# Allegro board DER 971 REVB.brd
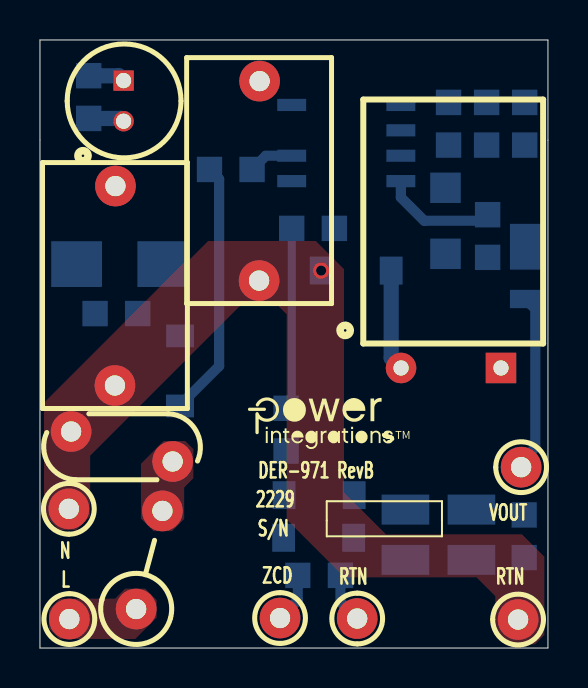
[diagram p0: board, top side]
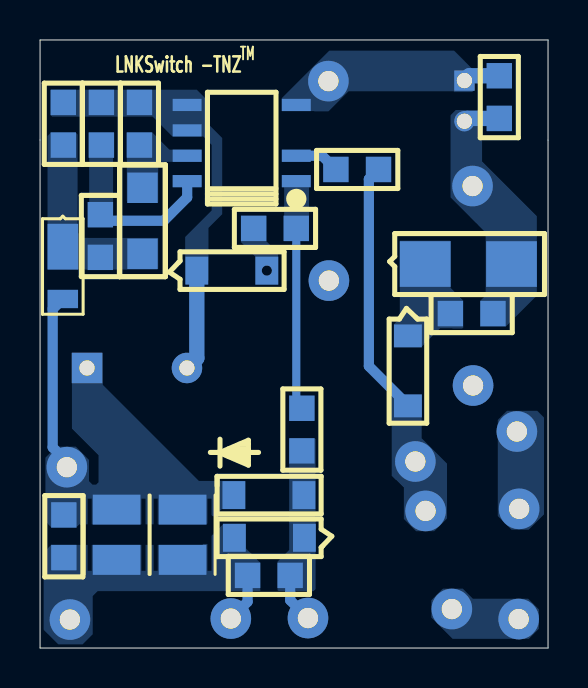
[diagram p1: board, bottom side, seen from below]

Outline 25.42 x 30.4 mm; copper layers: TOP, BOTTOM. Coordinates in mm from the lower left corner of the outline.
Outline path: 0,30.4 0,0 25.42,0 25.42,30.4 0,30.4

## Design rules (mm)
constraint set DEFAULT: min track width 0.508

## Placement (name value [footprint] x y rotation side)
C1  680 nF  [PINPCAPRAD12P3X7P3MM040]  10.97 28.37 270 top
C2  100 nF  [PISMC0805]  20.45 25.15 90 bottom
C3  10 uF  [PISMC0805]  24.26 25.15 90 bottom
C4  47 uF  [PISMC1411]  18.29 5.66 270 bottom
C5  100 pF  [PISMC0805]  12.6 20.98 0 bottom
C6  680 nF  [PINPCAPRAD12P3X7P3MM040]  3.75 23.13 270 top
C7  100 pF  [PISMC0805]  12.9 3.63 0 bottom
C10  47 uF  [PISMC1411]  21.59 5.66 270 bottom
D1  SM4007PL-TP  [PI_SM_SOD-123_12]  7.01 15.61 270 bottom
D2  ES1004FL_R1_00001  [PI_SM_SOD-123_12]  17.58 18.87 180 bottom
D3  DFLR1400-7  [PISMDDFLR120012]  24.28 20.09 90 bottom
D4  SM4001PL-TP  [PI_SM_SOD-123_12]  15.72 7.65 180 bottom
D5  SM4001PL-TP  [PI_SM_SOD-123_12]  12.19 5.51 0 bottom
L1  1000 uH  [PI_CHOKE_RLB9012_D2]  23.07 14 180 top
L2  2.2 mH  [PI_CHOKE_RL5480-1_D2]  4.18 28.37 270 top
NOREF  -  []  0 0 90 top
NOREF#2  -  []  0 0 0 top
NOREF#3  -  []  9.86 12.42 0 top
NOREF#4  -  []  -155.86 54.23 0 top
NOREF#5  -  []  -233.68 -144.78 0 top
R1  4.99 k  [PISMR0805]  2.76 16.72 0 bottom
R2  1 M  [PISMR0805]  10.62 23.93 180 bottom
R3  2 k  [PISMR1206]  20.29 23.02 270 bottom
R4  39.2 k  [PISMR0805]  22.35 25.15 90 bottom
R5  33.2 k  [PISMR0805]  22.4 19.54 90 bottom
R6  100 k  [PISMR0805]  12.32 11.99 270 bottom
R7  20 k  [PISMR0805]  24.23 6.65 270 bottom
R8  4.7 k  [PISMR0805]  2.44 26.48 90 bottom
RF1  8.2  [PI12WRESD180LS575040]  4.81 1.95 75 top
RV1  140 Vac  [PI_NP_CAP_RAD_320X120LS200D040]  6.64 9.3 180 top
TP1  BLK  [PITPKEYSTONE100X100]  1.47 1.45 0 top
TP2  WHT  [PITPKEYSTONE100X100]  1.45 6.96 0 top
TP3  RED  [PITPKEYSTONE100X100]  24.08 9.04 90 top
TP4  BLUE  [PITPKEYSTONE100X100]  12.01 1.5 0 top
TP5  BLK  [PITPKEYSTONE100X100]  23.93 1.42 90 top
TP6  BLK  [PITPKEYSTONE100X100]  15.87 1.47 0 top
U1  LNK3302  [PISMSO8_NOP3]  12.6 23.35 90 bottom
VR1  SMAZ10-13-F  [PISMDO214AC12]  6.15 19.2 180 bottom

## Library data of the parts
C1-C3 C5-C7 = CAP NP
C4 C10 = CAP POL: User Part Number: PN; Tolerance: TOL
D1-D3 = DIODE
D4 D5 = DIODE: room: 2
L1 L2 = INDUCTOR_DOT2
R1 R3 R5 = R
R2 R6 R8 = R: room: 1
R4 R7 = R: tolerance: 1%
RF1 = RF: alternate symbols: (pi1wvresd120ls200d040)
RV1 = VARISTOR
TP1 TP2 TP4-TP6 = TESTPOINT
TP3 = TESTPOINT: room: 2
U1 = LNK-TNZ
VR1 = DIODE_ZENER

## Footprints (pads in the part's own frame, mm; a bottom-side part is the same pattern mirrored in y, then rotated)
PI12WRESD180LS575040
  round 2.032 hole 1.016: 1(0,0) 2(5.08,0)
PI_CHOKE_RL5480-1_D2
  rect 1.016x1.016 hole 0.762: 1(0,0)
  round 1.016 hole 0.762: 2(2.032,0)
PI_CHOKE_RLB9012_D2
  rect 1.524x1.524 hole 0.762: 1(0,0)
  round 1.524 hole 0.762: 2(5.001,0)
PI_NP_CAP_RAD_320X120LS200D040
  round 2.032 hole 1.016: 1(0,-0.025) 2(5.08,-1.524)
PI_SM_SOD-123_12
  rect 1.143x1.397 smd: 1(0,0) 2(3.505,0)
PINPCAPRAD12P3X7P3MM040
  round 2.032 hole 1.016: 1(0.025,0.025) 2(10,0)
PISMC0805
  rect 1.27x1.27 smd: 1(0,0) 2(2.134,0)
PISMC1411
  rect 1.498x2.388 smd: 1(-1.258,0) 2(1.258,0)
PISMDDFLR120012
  rect 2.286x1.524 smd: 1(-0.025,0)
  rect 0.914x1.524 smd: 2(-2.642,0)
PISMDO214AC12
  rect 2.54x2.286 smd: 1(0,0) 2(4.318,0)
PISMR0805
  rect 1.27x1.27 smd: 1(0,0) 2(2.134,0)
PISMR1206
  rect 1.524x1.524 smd: 1(0,0) 2(3.302,0)
PISMSO8_NOP3
  rect 0.61x1.448 smd: 1(0,0) 2(1.27,0) 4(3.81,0) 5(3.81,5.461) 6(2.54,5.461) 7(1.27,5.461) 8(0,5.461)
PITPKEYSTONE100X100
  round 2.032 hole 1.016: 1(0,0)

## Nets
N361822: C1.2 C4.2 C5.2 C6.2 C7.2 C10.2 D2.2 D5.2 R7.2 RV1.2 TP2.1 TP5.1 TP6.1
N595771: D1.2 R2.2 RF1.2 RV1.1
N596154: RF1.1 TP1.1
N596955: C2.1 R3.1 U1.7
N596963: C3.1 D3.1 R3.2 R5.1
N597007: R4.1 R5.2 U1.8
N597039: C4.1 C10.1 D3.2 D4.1 L1.1 R7.1 TP3.1
N597129: C2.2 C3.2 D2.1 L1.2 R4.2 U1.5 U1.6
N597183: C1.1 L2.1 R8.2 U1.4
N605807: R2.1 U1.2
N607999: C7.1 D4.2 D5.1 R6.2 TP4.1
N609815: C5.1 R6.1 U1.1
N612476: C6.1 L2.2 R1.1 R8.1 VR1.2
N637767: D1.1 R1.2 VR1.1

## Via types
v1: diameter 0.813, hole 0.508, TOP to BOTTOM, 1 via

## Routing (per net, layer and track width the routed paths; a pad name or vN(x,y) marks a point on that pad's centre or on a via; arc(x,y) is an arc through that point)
N361822: length 2.5
  BOTTOM w0.508: C7.2 15.04,2.31 TP6.1
  vias: v1(14.07,18.87)
N595771: length 12.8
  BOTTOM w0.508: 7.01,12.12 7.01,12.14 8.97,14.1 8.97,23.45 R2.2
N597007: length 5.8
  BOTTOM w0.508: R5.2 22.38,21.69 22.05,21.36 19.23,21.36 18.06,22.53 U1.8
N597039: length 8.9
  BOTTOM w0.508: D3.2 24.79,16.94 24.79,10.03 24.08,9.32 TP3.1
N597129: length 5.1
  BOTTOM w0.762: L1.2 17.58,14.5 D2.1
N597183: length 1.8
  BOTTOM w0.762: R8.2 3.94,28.62 L2.1
N605807: length 2.3
  BOTTOM w0.508: R2.1 11.3,24.62 U1.2
N607999: length 2.5
  BOTTOM w0.508: C7.1 12.9,2.39 TP4.1
N609815: length 9.1
  BOTTOM w0.4: C5.1 12.6,12.27 R6.1
N612476: length 1.8
  BOTTOM w0.762: R8.1 4.04,26.48 L2.2

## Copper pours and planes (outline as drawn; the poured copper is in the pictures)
N361822 on TOP: 8.41,20.35 13.82,20.35 15.21,18.95 15.21,7.78 17.31,5.69 24.11,5.69 25.25,4.55 25.25,0.66 24.77,0.18 23.29,0.18 22.78,0.69 22.78,2.6 22.55,2.83 21.85,3.53 15.24,3.53 12.34,6.43 12.34,16.69 11.77,17.27 10.17,17.27 2.51,9.61 2.51,6.6 1.8,5.89 0.97,5.89 0.2,6.65 0.2,12.27 7.38,19.44 7.51,19.44
N361822 on BOTTOM: 25.24,0.91 24.51,0.18 23.29,0.18 22.78,0.69 22.78,2.6 22.54,2.84 14.4,2.84 14.4,4.27 15.14,5 15.14,6.2 16.26,6.2 17.3,5.16 24.87,5.16 25.24,4.78
N361822 on BOTTOM: 15.37,21.59 15.37,20.29 14.66,19.58 14.66,18.16 13.51,18.16 13.51,19.76 14.1,20.35 14.1,21.59
N361822 on BOTTOM: 0.2,6.68 0.2,11.53 0.53,11.86 2.06,11.86 2.51,11.4 2.51,6.6 1.83,5.92 0.97,5.92
N595771 on TOP: 5.05,6.48 5.05,9.22 6.18,10.35 7.29,10.35 7.29,10.34 7.67,9.96 7.67,8.48 7.21,8.03 7.21,6.45 6.6,5.84 5.69,5.84
N595771 on BOTTOM: 5.05,6.48 5.05,9.22 6.18,10.35 6.2,10.35 6.2,10.36 6.32,10.49 6.32,12.67 6.35,12.7 7.75,12.7 7.82,12.62 7.82,8.61 7.62,8.41 7.59,8.41 7.21,8.03 7.21,6.45 6.6,5.84 5.69,5.84
N596154 on TOP, BOTTOM: 0.97,0.46 4.78,0.46 5.84,1.52 5.84,2.39 5.26,2.97 4.27,2.97 3.76,2.46 0.99,2.46 0.46,1.93 0.46,0.97
N596955 on BOTTOM: 19.22,24.31 19.22,24.31 19.37,24.31 19.51,24.17 19.51,22.28 19.52,22.28 21,22.28 21.08,22.36 21.08,25.79 19.81,25.79 18.95,24.92 17.34,24.92 17.34,24.31
N596963 on BOTTOM: 19.51,20.51 23,20.51 23,20.51 23.27,20.51 23.54,20.78 23.54,25.69 23.63,25.77 24.88,25.77 25.04,25.61 25.04,18.93 19.56,18.93 19.51,18.98
N597007 on BOTTOM: 22.96,25.78 22.96,21.06 21.77,21.06 21.77,25.78
N597039 on BOTTOM: 15.16,6.96 16.22,6.96 16.22,6.95 16.33,6.95 17.09,6.18 23.46,6.18 23.62,6.02 24.85,6.02 25.15,6.32 25.15,9.52 24.6,10.07 23.63,10.07 22.97,9.41 22.97,8.34 22.79,8.17 22.62,8.17 22.5,8.29 22.5,9.64 23.83,10.97 23.83,14.68 23.75,14.76 22.28,14.76 22.28,13.16 17.47,8.35 15.16,8.35
N597129 on BOTTOM: 17.58,27.92 17.15,27.49 17.15,26.34 16.31,25.5 16.31,21.69 16.99,21.01 16.99,18.39 18.16,18.39 18.16,20.55 16.83,21.88 16.83,25.16 17.26,25.58 18.8,25.58 19.79,26.57 24.82,26.57 24.89,26.64 24.89,27.89 24.86,27.92
N597183 on BOTTOM: 13.32,26.85 11.71,26.85 11.7,26.84 10.98,26.84 9.98,27.84 4.72,27.84 4.69,27.8 3.8,27.8 3.71,27.89 3.71,28.88 4.7,29.87 10.95,29.87 13.32,27.5
N607999 on BOTTOM: 11.63,2.95 11.63,10.44 11.68,10.49 12.95,10.49 12.95,4.9 13.54,4.32 13.54,2.9 13.49,2.84 11.73,2.84
N609815 on BOTTOM: 13.21,20.35 13.21,23.65 11.96,23.65 11.96,20.35
N612476 on BOTTOM: 3.43,26.9 4.62,26.9 4.88,26.64 4.88,22.53 3.12,20.78 3.12,17.63 3.4,17.35 3.4,16.08 2.11,16.08 0.56,17.63 0.56,21.59 3.3,24.33 3.3,26.77
N637767 on BOTTOM: 7.42,20.37 7.42,16.48 7.72,16.18 7.72,15.04 6.35,15.04 5.4,15.99 4.81,15.99 4.8,15.98 4.29,15.98 4.24,16.03 4.24,17.37 4.88,18.01 4.88,20.35 4.9,20.37

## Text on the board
Ref Des/Silkscreen Bottom: TM | LNKSwitch -TNZ
Ref Des/Silkscreen Top: N | L | 2229 | S/N | DER-971 RevB | ZCD | RTN | VOUT
TOLERANCE_BOTTOM: 14.  FAB HOUSE LOGO,DATE CODE TO BE IN SILK SCREEN ONLY.DO NOT USE COPPER. | 13.  MATERIAL FR4 COPPER 2oz THICKNESS 0.062" | NOTES: PLEASE DELETE THESE PINS
User.8: FIGURE | FINISHED_SIZE | 20.0 | 30.0 | 40.0 | DRILL CHART: TOP to BOTTOM | ALL UNITS ARE IN MILS | TOLERANCE_DRILL | +3.0/-3.0 | PLATED | QTY | 1 | 4 | 14 | 19 | TOTAL HOLES:
